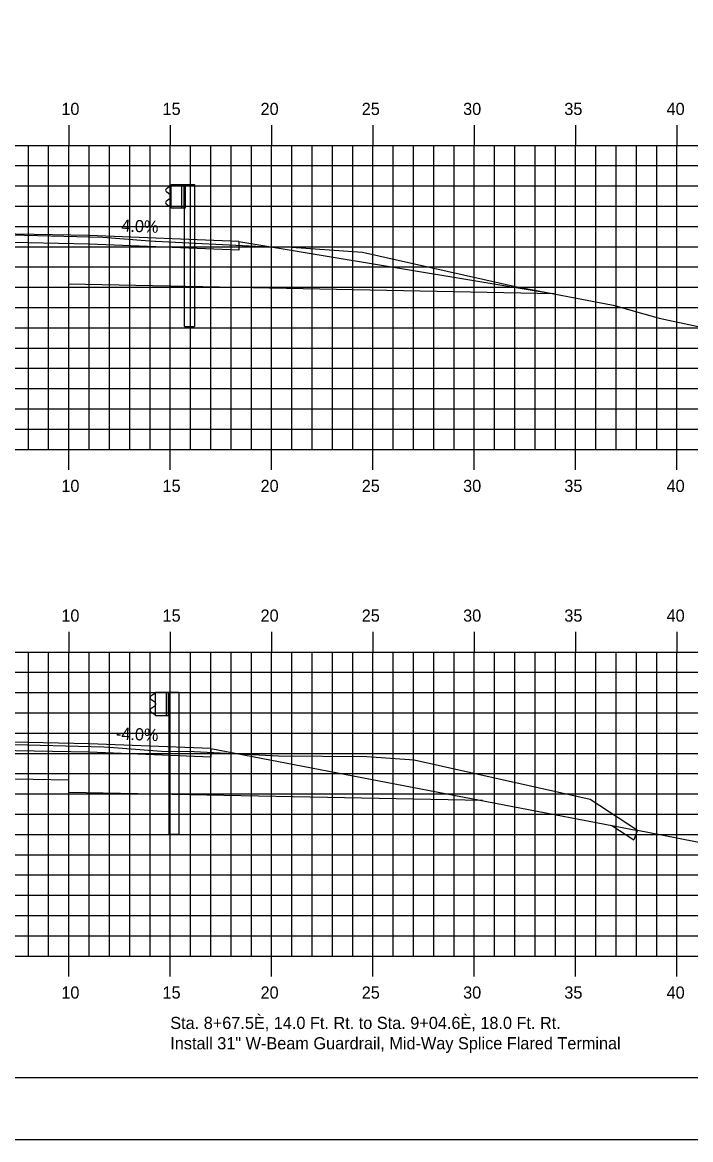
# Model space of a CAD drawing. Extents: x 2194502 to 2194968, y 863888 to 863998.
# Drawn here: x 2194706.2 to 2194739.2, y 863888.4 to 863943.5 of the extents above; entities that cross this region are included whole.
import ezdxf

# ---------------------------------------------------------------- set-up
doc = ezdxf.new("R2010")
doc.units = 0
for name, color, linetype in [('ANNOTATION', 7, 'Continuous'), ('BORDER', 7, 'Continuous'), ('D_Guardrail_Beam_Lt', 7, 'Continuous'), ('D_Guardrail_Beam_Rt', 7, 'Continuous'), ('H_V ANNOTATION', 7, 'Continuous'), ('MAJOR', 7, 'Continuous'), ('MINOR', 7, 'Continuous'), ('PLOT BOUNDARY', 7, 'Continuous'), ('S_Roadway_Centerline', 7, 'Continuous'), ('TEMPLATE', 7, 'Continuous')]:
    doc.layers.add(name, color=color, linetype=linetype)

msp = doc.modelspace()

# ---------------------------------------------------------------- linework, layer by layer
at = {"layer": 'BORDER'}
msp.add_lwpolyline([(2194623.499, 863891.446), (2194783.499, 863891.446), (2194783.499, 863996.446), (2194623.499, 863996.446)], close=True, dxfattribs=at)
at = {"layer": 'D_Guardrail_Beam_Lt'}
for p, q in [((2194713.538, 863935.512), (2194714.226, 863935.512)), ((2194713.538, 863934.345), (2194713.538, 863935.512)), ((2194714.059, 863935.512), (2194714.059, 863934.345)), ((2194714.163, 863935.512), (2194714.163, 863934.345)), ((2194714.226, 863935.512), (2194714.696, 863935.512)), ((2194714.226, 863935.512), (2194714.226, 863934.345)), ((2194714.696, 863935.512), (2194714.696, 863928.512)), ((2194713.448, 863935.407), (2194713.305, 863935.307)), ((2194713.305, 863935.164), (2194713.5, 863935.028)), ((2194713.538, 863935.428), (2194713.464, 863935.414)), ((2194713.534, 863934.963), (2194713.534, 863934.893)), ((2194713.5, 863934.829), (2194713.305, 863934.693)), ((2194713.305, 863934.55), (2194713.448, 863934.45)), ((2194713.464, 863934.443), (2194713.538, 863934.428)), ((2194714.226, 863934.345), (2194713.538, 863934.345)), ((2194714.205, 863928.512), (2194714.205, 863934.345)), ((2194714.205, 863928.512), (2194714.696, 863928.512))]:
    msp.add_line(p, q, dxfattribs=at)
for centre, major_axis, start_param, end_param in [((2194713.355, 863935.236), (-0.0877, 0), 5.323254, 7.243116), ((2194713.472, 863935.373), (-0.0417, 0), 4.907132, 5.323254), ((2194713.455, 863934.963), (0.0789, 0), 0, 0.959931), ((2194713.355, 863934.621), (-0.0877, 0), 5.323254, 7.243116), ((2194713.472, 863934.484), (-0.0417, 0), 0.959931, 1.376053), ((2194713.455, 863934.893), (0.0789, 0), 5.323254, 6.283185)]:
    msp.add_ellipse(centre, major_axis=major_axis, ratio=0.995501, start_param=start_param, end_param=end_param, dxfattribs=at)
at = {"layer": 'D_Guardrail_Beam_Rt'}
for p, q in [((2194712.68, 863910.362), (2194712.537, 863910.262)), ((2194712.537, 863910.119), (2194712.732, 863909.982)), ((2194712.77, 863910.383), (2194712.696, 863910.368)), ((2194712.77, 863910.466), (2194713.458, 863910.466)), ((2194712.77, 863909.3), (2194712.77, 863910.466)), ((2194713.291, 863910.466), (2194713.291, 863909.3)), ((2194713.395, 863910.466), (2194713.395, 863909.3)), ((2194713.458, 863910.466), (2194713.928, 863910.466)), ((2194713.458, 863910.466), (2194713.458, 863909.3)), ((2194713.928, 863910.466), (2194713.928, 863903.466)), ((2194712.732, 863909.783), (2194712.537, 863909.647)), ((2194712.766, 863909.918), (2194712.766, 863909.848)), ((2194712.537, 863909.504), (2194712.68, 863909.404)), ((2194712.696, 863909.397), (2194712.77, 863909.383)), ((2194713.458, 863909.3), (2194712.77, 863909.3)), ((2194713.437, 863903.466), (2194713.437, 863909.3)), ((2194713.437, 863903.466), (2194713.928, 863903.466))]:
    msp.add_line(p, q, dxfattribs=at)
for centre, major_axis, start_param, end_param in [((2194712.587, 863910.19), (-0.0877, 0), 5.323254, 7.243116), ((2194712.704, 863910.328), (-0.0417, 0), 4.907132, 5.323254), ((2194712.587, 863909.576), (-0.0877, 0), 5.323254, 7.243116), ((2194712.687, 863909.918), (0.0789, 0), 0, 0.959931), ((2194712.687, 863909.848), (0.0789, 0), 5.323254, 6.283185), ((2194712.704, 863909.438), (-0.0417, 0), 0.959931, 1.376053)]:
    msp.add_ellipse(centre, major_axis=major_axis, ratio=0.995501, start_param=start_param, end_param=end_param, dxfattribs=at)
at = {"layer": 'MAJOR'}
for p, q in [((2194708.499, 863938.448), (2194708.499, 863937.446)), ((2194713.499, 863938.448), (2194713.499, 863937.446)), ((2194718.499, 863938.448), (2194718.499, 863937.446)), ((2194723.499, 863938.448), (2194723.499, 863937.446)), ((2194728.499, 863938.448), (2194728.499, 863937.446)), ((2194733.499, 863938.448), (2194733.499, 863937.446)), ((2194738.499, 863938.448), (2194738.499, 863937.446)), ((2194628.499, 863937.446), (2194768.499, 863937.446)), ((2194708.499, 863922.446), (2194708.499, 863937.446)), ((2194713.499, 863922.446), (2194713.499, 863937.446)), ((2194718.499, 863922.446), (2194718.499, 863937.446)), ((2194723.499, 863922.446), (2194723.499, 863937.446)), ((2194728.499, 863922.446), (2194728.499, 863937.446)), ((2194733.499, 863922.446), (2194733.499, 863937.446)), ((2194738.499, 863922.446), (2194738.499, 863937.446)), ((2194628.499, 863932.446), (2194768.499, 863932.446)), ((2194628.499, 863927.446), (2194768.499, 863927.446)), ((2194628.499, 863922.446), (2194768.499, 863922.446)), ((2194708.499, 863921.444), (2194708.499, 863922.446)), ((2194713.499, 863921.444), (2194713.499, 863922.446)), ((2194718.499, 863921.444), (2194718.499, 863922.446)), ((2194723.499, 863921.444), (2194723.499, 863922.446)), ((2194728.499, 863921.444), (2194728.499, 863922.446)), ((2194733.499, 863921.444), (2194733.499, 863922.446)), ((2194738.499, 863921.444), (2194738.499, 863922.446)), ((2194708.499, 863913.448), (2194708.499, 863912.446)), ((2194713.499, 863913.448), (2194713.499, 863912.446)), ((2194718.499, 863913.448), (2194718.499, 863912.446)), ((2194723.499, 863913.448), (2194723.499, 863912.446)), ((2194728.499, 863913.448), (2194728.499, 863912.446)), ((2194733.499, 863913.448), (2194733.499, 863912.446)), ((2194738.499, 863913.448), (2194738.499, 863912.446)), ((2194628.499, 863912.446), (2194768.499, 863912.446)), ((2194708.499, 863897.446), (2194708.499, 863912.446)), ((2194713.499, 863897.446), (2194713.499, 863912.446)), ((2194718.499, 863897.446), (2194718.499, 863912.446)), ((2194723.499, 863897.446), (2194723.499, 863912.446)), ((2194728.499, 863897.446), (2194728.499, 863912.446)), ((2194733.499, 863897.446), (2194733.499, 863912.446)), ((2194738.499, 863897.446), (2194738.499, 863912.446)), ((2194628.499, 863907.446), (2194768.499, 863907.446)), ((2194628.499, 863902.446), (2194768.499, 863902.446)), ((2194628.499, 863897.446), (2194768.499, 863897.446)), ((2194708.499, 863896.444), (2194708.499, 863897.446)), ((2194713.499, 863896.444), (2194713.499, 863897.446)), ((2194718.499, 863896.444), (2194718.499, 863897.446)), ((2194723.499, 863896.444), (2194723.499, 863897.446)), ((2194728.499, 863896.444), (2194728.499, 863897.446)), ((2194733.499, 863896.444), (2194733.499, 863897.446)), ((2194738.499, 863896.444), (2194738.499, 863897.446))]:
    msp.add_line(p, q, dxfattribs=at)
at = {"layer": 'MINOR'}
for p, q in [((2194706.499, 863922.446), (2194706.499, 863937.446)), ((2194707.499, 863922.446), (2194707.499, 863937.446)), ((2194709.499, 863922.446), (2194709.499, 863937.446)), ((2194710.499, 863922.446), (2194710.499, 863937.446)), ((2194711.499, 863922.446), (2194711.499, 863937.446)), ((2194712.499, 863922.446), (2194712.499, 863937.446)), ((2194714.499, 863922.446), (2194714.499, 863937.446)), ((2194715.499, 863922.446), (2194715.499, 863937.446)), ((2194716.499, 863922.446), (2194716.499, 863937.446)), ((2194717.499, 863922.446), (2194717.499, 863937.446)), ((2194719.499, 863922.446), (2194719.499, 863937.446)), ((2194720.499, 863922.446), (2194720.499, 863937.446)), ((2194721.499, 863922.446), (2194721.499, 863937.446)), ((2194722.499, 863922.446), (2194722.499, 863937.446)), ((2194724.499, 863922.446), (2194724.499, 863937.446)), ((2194725.499, 863922.446), (2194725.499, 863937.446)), ((2194726.499, 863922.446), (2194726.499, 863937.446)), ((2194727.499, 863922.446), (2194727.499, 863937.446)), ((2194729.499, 863922.446), (2194729.499, 863937.446)), ((2194730.499, 863922.446), (2194730.499, 863937.446)), ((2194731.499, 863922.446), (2194731.499, 863937.446)), ((2194732.499, 863922.446), (2194732.499, 863937.446)), ((2194734.499, 863922.446), (2194734.499, 863937.446)), ((2194735.499, 863922.446), (2194735.499, 863937.446)), ((2194736.499, 863922.446), (2194736.499, 863937.446)), ((2194737.499, 863922.446), (2194737.499, 863937.446)), ((2194628.499, 863936.446), (2194768.499, 863936.446)), ((2194628.499, 863935.446), (2194768.499, 863935.446)), ((2194628.499, 863934.446), (2194768.499, 863934.446)), ((2194628.499, 863933.446), (2194768.499, 863933.446)), ((2194628.499, 863931.446), (2194768.499, 863931.446)), ((2194628.499, 863930.446), (2194768.499, 863930.446)), ((2194628.499, 863929.446), (2194768.499, 863929.446)), ((2194628.499, 863928.446), (2194768.499, 863928.446)), ((2194628.499, 863926.446), (2194768.499, 863926.446)), ((2194628.499, 863925.446), (2194768.499, 863925.446)), ((2194628.499, 863924.446), (2194768.499, 863924.446)), ((2194628.499, 863923.446), (2194768.499, 863923.446)), ((2194706.499, 863897.446), (2194706.499, 863912.446)), ((2194707.499, 863897.446), (2194707.499, 863912.446)), ((2194709.499, 863897.446), (2194709.499, 863912.446)), ((2194710.499, 863897.446), (2194710.499, 863912.446)), ((2194711.499, 863897.446), (2194711.499, 863912.446)), ((2194712.499, 863897.446), (2194712.499, 863912.446)), ((2194714.499, 863897.446), (2194714.499, 863912.446)), ((2194715.499, 863897.446), (2194715.499, 863912.446)), ((2194716.499, 863897.446), (2194716.499, 863912.446)), ((2194717.499, 863897.446), (2194717.499, 863912.446)), ((2194719.499, 863897.446), (2194719.499, 863912.446)), ((2194720.499, 863897.446), (2194720.499, 863912.446)), ((2194721.499, 863897.446), (2194721.499, 863912.446)), ((2194722.499, 863897.446), (2194722.499, 863912.446)), ((2194724.499, 863897.446), (2194724.499, 863912.446)), ((2194725.499, 863897.446), (2194725.499, 863912.446)), ((2194726.499, 863897.446), (2194726.499, 863912.446)), ((2194727.499, 863897.446), (2194727.499, 863912.446)), ((2194729.499, 863897.446), (2194729.499, 863912.446)), ((2194730.499, 863897.446), (2194730.499, 863912.446)), ((2194731.499, 863897.446), (2194731.499, 863912.446)), ((2194732.499, 863897.446), (2194732.499, 863912.446)), ((2194734.499, 863897.446), (2194734.499, 863912.446)), ((2194735.499, 863897.446), (2194735.499, 863912.446)), ((2194736.499, 863897.446), (2194736.499, 863912.446)), ((2194737.499, 863897.446), (2194737.499, 863912.446)), ((2194628.499, 863911.446), (2194768.499, 863911.446)), ((2194628.499, 863910.446), (2194768.499, 863910.446)), ((2194628.499, 863909.446), (2194768.499, 863909.446)), ((2194628.499, 863908.446), (2194768.499, 863908.446)), ((2194628.499, 863906.446), (2194768.499, 863906.446)), ((2194628.499, 863905.446), (2194768.499, 863905.446)), ((2194628.499, 863904.446), (2194768.499, 863904.446)), ((2194628.499, 863903.446), (2194768.499, 863903.446)), ((2194628.499, 863901.446), (2194768.499, 863901.446)), ((2194628.499, 863900.446), (2194768.499, 863900.446)), ((2194628.499, 863899.446), (2194768.499, 863899.446)), ((2194628.499, 863898.446), (2194768.499, 863898.446))]:
    msp.add_line(p, q, dxfattribs=at)
at = {"layer": 'PLOT BOUNDARY'}
msp.add_lwpolyline([(2194615.406, 863888.387), (2194785.406, 863888.387), (2194785.406, 863998.387), (2194615.406, 863998.387)], close=True, dxfattribs=at)
at = {"layer": 'S_Roadway_Centerline'}
for points in [[(2194628.499, 863931.248), (2194644.102, 863931.812), (2194651.913, 863930.949), (2194668.077, 863929.672), (2194681.104, 863932.691), (2194681.74, 863932.878), (2194687.144, 863933.179), (2194687.162, 863933.181), (2194691.811, 863933.191), (2194698.499, 863933.212), (2194698.585, 863933.211), (2194710.18, 863932.915), (2194712.278, 863932.755), (2194712.76, 863932.719), (2194712.774, 863932.719), (2194718.053, 863932.454), (2194719.251, 863932.444), (2194722.99, 863932.169), (2194730.529, 863930.489), (2194735.351, 863929.559), (2194737.618, 863928.913), (2194750.8, 863926.104), (2194768.499, 863925.832)], [(2194667.598, 863903.809), (2194672.818, 863905.013), (2194682.058, 863907.726), (2194686.684, 863907.983), (2194687.208, 863908.025), (2194696.988, 863908.045), (2194698.48, 863908.066), (2194700.167, 863908.027), (2194710.222, 863907.77), (2194710.933, 863907.72), (2194713.063, 863907.563), (2194714.672, 863907.54), (2194718.844, 863907.33), (2194723.196, 863907.293), (2194725.536, 863907.121), (2194734.215, 863905.192), (2194736.558, 863903.65), (2194738.492, 863903.278), (2194745.923, 863901.819), (2194754.026, 863901.226), (2194762.901, 863901.073), (2194768.499, 863901.043)]]:
    msp.add_lwpolyline(points, dxfattribs=at)
at = {"layer": 'TEMPLATE'}
for p, q in [((2194709.499, 863932.996), (2194698.499, 863933.216)), ((2194709.499, 863932.579), (2194698.499, 863932.799)), ((2194716.887, 863932.7), (2194709.499, 863932.996)), ((2194716.887, 863932.7), (2194732.44, 863930.12)), ((2194709.499, 863907.92), (2194698.499, 863908.14)), ((2194715.499, 863907.68), (2194709.499, 863907.92)), ((2194709.499, 863907.503), (2194698.499, 863907.723)), ((2194715.499, 863907.68), (2194736.56, 863903.648)), ((2194708.499, 863906.123), (2194698.499, 863906.323)), ((2194736.558, 863903.65), (2194736.365, 863903.178))]:
    msp.add_line(p, q, dxfattribs=at)
for points in [[(2194732.44, 863930.12), (2194708.499, 863930.599), (2194708.499, 863932.599)], [(2194716.887, 863932.7), (2194716.887, 863932.284), (2194709.499, 863932.579)], [(2194715.499, 863907.68), (2194715.499, 863907.263), (2194709.499, 863907.503)], [(2194728.898, 863905.115), (2194708.499, 863905.523), (2194708.499, 863906.123)], [(2194735.278, 863903.894), (2194736.365, 863903.178)]]:
    msp.add_lwpolyline(points, dxfattribs=at)

# ---------------------------------------------------------------- texts
at = {"layer": 'ANNOTATION'}
for p in [(2194710.808, 863933.21), (2194710.808, 863908.134)]:
    msp.add_text('-4.0%', height=0.6, rotation=357.7094, dxfattribs=at).set_placement(p)
for s, p in [('Sta. 8+67.5È, 14.0 Ft. Rt. to Sta. 9+04.6È, 18.0 Ft. Rt.', (2194713.499, 863893.846)), ('Install 31" W-Beam Guardrail, Mid-Way Splice Flared Terminal', (2194713.499, 863892.844))]:
    msp.add_text(s, height=0.6, dxfattribs=at).set_placement(p)
at = {"layer": 'H_V ANNOTATION'}
for s, p in [('10', (2194708.125, 863938.946)), ('15', (2194713.117, 863938.946)), ('20', (2194717.953, 863938.946)), ('25', (2194722.945, 863938.946)), ('30', (2194727.948, 863938.946)), ('35', (2194732.94, 863938.946)), ('40', (2194737.985, 863938.946)), ('10', (2194708.125, 863920.346)), ('15', (2194713.117, 863920.346)), ('20', (2194717.953, 863920.346)), ('25', (2194722.945, 863920.346)), ('30', (2194727.948, 863920.346)), ('35', (2194732.94, 863920.346)), ('40', (2194737.985, 863920.346)), ('10', (2194708.125, 863913.946)), ('15', (2194713.117, 863913.946)), ('20', (2194717.953, 863913.946)), ('25', (2194722.945, 863913.946)), ('30', (2194727.948, 863913.946)), ('35', (2194732.94, 863913.946)), ('40', (2194737.985, 863913.946)), ('10', (2194708.125, 863895.346)), ('15', (2194713.117, 863895.346)), ('20', (2194717.953, 863895.346)), ('25', (2194722.945, 863895.346)), ('30', (2194727.948, 863895.346)), ('35', (2194732.94, 863895.346)), ('40', (2194737.985, 863895.346))]:
    msp.add_text(s, height=0.6, dxfattribs=at).set_placement(p)

doc.saveas('drawing.dxf')
